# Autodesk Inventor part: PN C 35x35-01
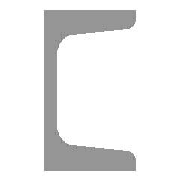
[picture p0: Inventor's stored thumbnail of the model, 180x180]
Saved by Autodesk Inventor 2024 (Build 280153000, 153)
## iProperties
Company: ATC
IsCustomPart: 1
Created: 2023-03
Part Number: PN C 35x35-01
Material: Ogólny
Description: Ceownik
Document SubType Name: Modeling
Standard: PN-86/H-93403
Designer: Andrzej Jaskulski
Standards Organization: PN
Language: pl-PL
Size Designation: C 35x35
Categories: <MemberInstance><Categories><Category DisplayName="Kształtowniki konstrukcyjne" InternalName="089c4875-fa83-4c05-b084-43b9cc11f5ed" Mnemonic="GRDR"><CategoryPar
Stock Number: C 35x35
Density: 1 g/cm^3
Appearance: Kurs-AJ
Checked By: A.J.
Engr Approved By: Andrzej Jaskulski
Mfg Approved By: Andrzej Jaskulski
Authority: A.J.
_CCFamilyMember: 10
_CCFamilyDisplayName: PN-86/H-93403 - Ceownik
_FrameMemberDoc: Frame Member File
_Version: 25.0.0
G_L: 160,000 mm
G_W: 35,000 mm
G_H: 35,000 mm
+50356EDF-CAC9-44D9-8C18-2E8D81CB3D2A+CUTDETAIL1: Połączenie narożne
Author: Andrzej Jaskulski
Title: A.J.: Kurs R2024-MEP
Revision Number: 1/24
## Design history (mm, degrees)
node "Płaszczyzna początkowa"
node "Płaszczyzna końcowa"
sketch "Szkic"
  geometry: L1 (0, 0)-(0, 17.5); L2 (0, 17.5)-(35, 17.5); L3 (35, 17.5)-(35, 15.47); L4 (32.239, 12.479)-(10.522, 10.742); L5 (5, 4.761)-(5, 0); L6 (5, 0)-(0, 0); L7 (20, 17.5)-(20, 11.5); L8 (35, 12.7)-(35, 11.5); L9 (35, 11.5)-(20, 11.5); L10 (0, 15)-(0, -27); L11 (-5.539, 0)-(16.007, 0); L12 (0, 0)-(0, -17.5); L13 (0, -17.5)-(35, -17.5); L14 (35, -17.5)-(35, -15.47); L15 (32.239, -12.479)-(10.522, -10.742); L16 (5, -4.761)-(5, 0); L17 (0, 26.4)-(0, -35.9) reference; L18 (-13.764, 0)-(43.809, 0) reference; A1 r 6 centre (11, 4.761) between (10.522, 10.742) and (5, 4.761); A2 r 6 centre (11, -4.761) between (5, -4.761) and (10.522, -10.742); A3 r 3 centre (32, 15.47) between (32.239, 12.479) and (35, 15.47); A4 r 3 centre (32, -15.47) between (35, -15.47) and (32.239, -12.479); 5 further points
  constraints: 32 end point, 12 point on line, 8 point on circle, 8 tangent, 6 symmetric about line, 4 centre point, 4 parallel, 3 collinear, 3 perpendicular, 2 equal radius, 5 other
  dimensions: "d0" = 5 distance between parallel lines of L1 L5 (= G_T); "d1" = 17.5 distance between parallel lines of L6 L2 (= 0.5 x G_H); "d2" = 35 distance between parallel lines of L3 L1 (= G_W); "d3" = 6 distance of L2.end L8.end (= G_T1); "d4" = 15 distance of L7.start L2.end (= G_C); "d5" = 1.2 distance of L8.start L8.end (computed from G_NG, G_C); "d23" = 6 radius of A1 (= G_IR); "d24" = 3 radius of A3 (= G_ER); "d25" = 0 distance between parallel lines of L10 L12 (computed from ex)
extrude "Bryła" new body sketch "Szkic" stored distance "d6" = 160 (= G_L); taper "d7" = 0 deg
node "Driven Length"
  sketch "Sketch3"
    geometry: L1 (0, 0)-(10, 0) reference
    constraints: 2 end point, 1 horizontal
  workplane "Work Plane3"
node "Płaszczyzna konstrukcyjna4"
feature "Podział1"
body "Solid1"
sketch "Sketch4"
  geometry: L1 (-2, 40)-(12, 40) reference; L2 (-2, 200)-(12, 200) reference
  dimensions: "d29" = 160 distance between parallel lines of L1 L2 (derived)
other parameters: "G_W" = 35 [user parameter; used in 1 equation term], "G_H" = 35 [user parameter; used in 1 equation term], "G_T" = 5 [user parameter; used in 1 equation term], "G_T1" = 6 [user parameter; used in 1 equation term], "G_NG" = 0.8 [user parameter; used in 1 equation term], "G_ER" = 3 [user parameter; used in 1 equation term], "G_IR" = 6 [user parameter; used in 1 equation term], "G_C" = 15 [user parameter; used in 2 equation terms], "G_L" = 160 (= d29) [user parameter; used in 1 equation term], "ex" = 0 [user parameter; used in 1 equation term], "G_OFFSET_END" = 0 [user parameter; used in 1 equation term], "d28" = 90 deg
